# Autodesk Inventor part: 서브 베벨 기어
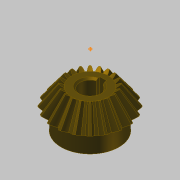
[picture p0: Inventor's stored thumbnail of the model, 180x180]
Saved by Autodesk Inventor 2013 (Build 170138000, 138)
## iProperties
Created: 2016-04
Part Number: 서브 베벨 기어
Material: 강철, 탄소
Document SubType Name: Modeling
Designer: mdu
Categories: <?xml version="1.0" encoding="UTF-16"?> <MemberInstance><Categories><FamilyTemplate><FamilyTemplateParameter ValueType="xs:double" Id="1" ObjectReferenceKey="da
Mass: 135.037 g
Surface Area: 63.6518 cm^2
Volume: 17.1585 cm^3
Density: 7.87 g/cm^3
CustomPartVersion: 1
Author: mdu
Revision Number: 1
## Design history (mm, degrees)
node "맨 위 점"
node "메쉬 평면2"
sketch "톱니 본체 스케치"
  geometry: L1 (0, 0)-(18.003, -31.331); L2 (18.003, -31.331)-(21.664, -28.891); L3 (21.664, -28.891)-(0, 0); L4 (20, -30)-(0, 0); L5 (10.813, -18.818)-(13.012, -17.352); L6 (18.003, -31.331)-(10.813, -18.818); L7 (21.664, -28.891)-(13.012, -17.352); L8 (0, -39.387)-(0, 6.564) reference; L9 (0, -30)-(21.664, -30)
  constraints: 16 end point, 4 point on line, 3 perpendicular, 2 collinear, 1 horizontal alignment, 1 vertical alignment
  dimensions: "d0" = 40 diameter of L4.start L8 (= da_de); "d1" = 36.00616 diameter of L1.end L8 (= da_dfe); "d2" = 43.3282 diameter of L2.end L8 (= da_dae); "d3" = 14.4 distance between parallel lines of L2 L5 (= da_b); "d4" = 28.8906 vertical distance of L2.end L1.start (= da_ve)
revolve "톱니 본체" sketch "톱니 본체 스케치" stored, may be unused: angle "d5" = 90 deg
node "시작점"
node "톱니 평면"
sketch "시작 스케치"
  geometry: L1 (0, -23.505)-(0, 10.645) reference; L2 (-0.834, -2.928)-(0.834, -2.928); A1 r 8.898 centre (-9.698, -3.713) between (-0.834, -2.928) and (-3.903, 3.04); A2 r 8.898 centre (9.698, -3.713) between (3.903, 3.04) and (0.834, -2.928); A3 r 27.357 centre (0, -24.037) between (3.903, 3.04) and (-3.903, 3.04); 1 further point
  constraints: 6 point on circle, 3 centre point, 3 symmetric about line, 2 end point, 1 coincident, 1 perpendicular, 1 other
  dimensions: "d7" = 8.89846 radius of A1 (= fd_rr); "d8" = 9.69794 horizontal distance of point (0, -24.037) A1.centre (= fd_x); "d9" = 20.32439 vertical distance of point (0, -24.037) A1.centre (= fd_y); "d57" = 27.35701 radius of A3 (= 0.5 x fd_dva + 0.3 x da_he); "d58" = 21.10901 distance from line of A3.centre L2 (= 0.5 x fd_dva - 1.12 x da_he)
node "끝점"
  node "끝 평면"
sketch "3D 스케치 오른쪽"
  node "Helical Curve Right" dims "d65" = 229.90621 (computed from da_dm, da_delta, da_beta), "d66" = 31.5, "d67" = 40 (= da_de), "d68" = -5.88003 (= -da_delta), "d69" = 12.16458 (computed from fd_loft, da_delta)
node "끝 평면 오른쪽"
sketch "끝 스케치 오른쪽"
  geometry: L1 (0, -22.649)-(0, 12.15) reference; L2 (-0.497, -1.72)-(0.497, -1.72); A1 r 5.299 centre (-5.775, -2.187) between (-0.497, -1.72) and (-2.324, 1.834); A2 r 5.299 centre (5.775, -2.187) between (2.324, 1.834) and (0.497, -1.72); A3 r 16.291 centre (0, -14.29) between (2.324, 1.834) and (-2.324, 1.834); 1 further point
  constraints: 6 point on circle, 3 centre point, 3 symmetric about line, 2 end point, 1 coincident, 1 perpendicular, 1 other
  dimensions: "d70" = 5.77526 horizontal distance of A3.centre A1.centre (computed from fd_x, fd_ratio); "d71" = 12.10346 vertical distance of point (0, -14.29) A1.centre (computed from fd_y, fd_ratio); "d72" = 5.29916 radius of A1 (computed from fd_rr, fd_ratio); "d73" = 12.57071 distance from line of point (0, -14.29) L2 (computed from d58, fd_ratio); "d74" = 16.29149 radius of A3 (computed from d57, fd_ratio)
feature "로프트 오른쪽" sketch "끝 스케치 오른쪽" dims "d75" = 0, "d77" = 0, "d79" = 0, "d80" = 90 deg, "d85" = 20, "d92" = 90 deg, "d93" = 90 deg, "da_teethtype" = 0 [user parameter]
sketch "3D 스케치 왼쪽"
  node "Helical Curve Left" dims "d26" = 229.90621 (computed from da_dm, da_delta, da_beta), "d27" = 12.16458 (computed from fd_loft, da_delta), "d28" = 40 (= da_de), "d29" = -5.88003 (= -da_delta)
node "끝 평면 왼쪽"
sketch "끝 스케치 왼쪽" dims "d56" = 10.82768 (derived)
  geometry: L1 (0, -35.087)-(0, 18.089) reference; L2 (-0.497, -1.716)-(0.497, -1.716); A1 r 5.299 centre (-5.775, -2.183) between (-0.497, -1.716) and (-2.324, 1.838); A2 r 5.299 centre (5.775, -2.183) between (2.324, 1.838) and (0.497, -1.716); A3 r 16.291 centre (0, -14.287) between (2.324, 1.838) and (-2.324, 1.838); 2 further points; 1 other entity
  constraints: 6 point on circle, 3 centre point, 3 symmetric about line, 2 end point, 1 coincident, 2 other
  dimensions: "d30" = 5.29916 radius of A1 (computed from fd_rr, fd_ratio); "d31" = 5.77526 horizontal distance of point (0, -14.287) A1.centre (computed from fd_x, fd_ratio); "d32" = 12.10346 vertical distance of A1.centre point (0, -14.287) (computed from fd_y, fd_ratio); "d61" = 16.29149 radius of A3 (computed from d57, fd_ratio); "d62" = 12.57071 distance from line of point (0, -14.287) L2 (computed from d58, fd_ratio)
feature "로프트 왼쪽" sketch "끝 스케치 왼쪽" dims "d35" = 0, "d37" = 0, "d39" = 0, "d40" = 90 deg, "d84" = 10, "d90" = 90 deg, "d91" = 90 deg, "da_teethtype" = 0 [user parameter]
sketch "본체 스케치"
  geometry: L1 (0, -35.038)-(0, -19.531) reference; L2 (18.003, -31.331)-(10.813, -18.818) reference; L3 (10.813, -18.818)-(0, -18.818); L4 (18.003, -31.331)-(0, -31.331)
  constraints: 4 end point, 2 perpendicular, 2 point on line
revolve "본체 고정" sketch "본체 스케치" stored, may be unused: angle "d46" = 90 deg
feature "피치 지름" dims angle "d47" = 90 deg
sketch "스케치8"
  geometry: C1 r 17 at (0, 0); 1 further point
  constraints: 1 centre point, 1 coincident
  dimensions: "d94" = 34 diameter of C1
extrude "돌출1" join sketch "스케치8" distance "d95" = 10; taper "d96" = 0 deg
sketch "스케치9"
  geometry: 1 further point
hole "구멍1" sketch "스케치9" at (0, 0) diameter "d97" = 12; stored, may be unused: countersink angle "d101" = 90 deg, drill point angle "d103" = 118 deg; dims "d98" = 6, "d99" = 4, "d100" = 2, "d102" = 8
sketch "스케치10"
  geometry: 1 further point
sketch "스케치11"
  geometry: 1 further point
sketch "스케치12"
  geometry: L1 (-2, 5.657)-(-2, 7.8); L2 (-2, 7.8)-(2, 7.8); L3 (2, 7.8)-(2, 5.657); A1 r 6 centre (0, 0) between (-2, 5.657) and (2, 5.657) reference; 1 further point
  constraints: 6 end point, 2 parallel, 2 point on circle, 1 perpendicular, 1 vertical
  dimensions: "d104" = 4 distance of L1.end L2.end; "d105" = 13.8 dimension on A1 L2
extrude "돌출2" cut sketch "스케치12" stored distance "d106" = 7; taper "d107" = 0 deg
chamfer "모따기1" distance "d108" = 1; stored, may be unused: second distance "d109" = 2, angle "d110" = 45 deg
body "Solid1"
feature "로프트" dims "d17" = 0, "d18" = 90 deg, "d19" = 0, "d20" = 90 deg, "d89" = 0, "da_teethtype" = 0 [user parameter]
pattern_circular "원형 패턴" dims angle "d22" = 360 deg, "d88" = 0, "da_teethtype" = 0 [user parameter]
pattern_circular "원형 패턴 오른쪽" dims angle "d82" = 360 deg, "da_teethtype" = 0 [user parameter]
pattern_circular "원형 패턴 왼쪽" dims angle "d42" = 360 deg, "da_teethtype" = 0 [user parameter]
sketch "끝 스케치"
  geometry: L1 (0, -15.359)-(0, 6.983) reference; L2 (-0.497, -1.72)-(0.497, -1.72); A1 r 5.299 centre (-5.775, -2.187) between (-0.497, -1.72) and (-2.324, 1.834); A2 r 5.299 centre (5.775, -2.187) between (2.324, 1.834) and (0.497, -1.72); A3 r 16.291 centre (0, -14.29) between (2.324, 1.834) and (-2.324, 1.834); 1 further point
  constraints: 6 point on circle, 3 centre point, 3 symmetric about line, 2 end point, 1 coincident, 1 other
  dimensions: "d12" = 5.29916 radius of A1 (computed from fd_rr, fd_ratio); "d15" = 5.77526 horizontal distance of A1.centre point (0, -14.29) (computed from fd_x, fd_ratio); "d16" = 12.10346 vertical distance of A1.centre point (0, -14.29) (computed from fd_y, fd_ratio); "d59" = 16.29149 radius of A3 (computed from d57, fd_ratio); "d60" = 12.57071 distance from line of A3.centre L2 (computed from d58, fd_ratio)
sketch "Sketch6"
  geometry: L1 (20, -30)-(0, 0) reference; L2 (0, -37.8)-(0, 6.3) reference
body "Srf1"
other parameters: "da_b" = 14.4 [user parameter; used in 2 equation terms], "da_de" = 40 [user parameter; used in 4 equation terms], "da_dae" = 43.3282 [user parameter; used in 2 equation terms], "da_dfe" = 36.00616 [user parameter; used in 1 equation term], "da_le" = 36.05551 [user parameter; used in 1 equation term], "da_omega" = 90 deg [user parameter; used in 1 equation term], "da_beta" = 0 [user parameter; used in 2 equation terms], "da_delta" = 5.88003 [user parameter; used in 8 equation terms], "da_alpha" = 20 deg [user parameter; used in 2 equation terms], "da_he" = 4.4 [user parameter; used in 4 equation terms], "da_ve" = 28.8906 [user parameter; used in 1 equation term], "fd_dv" = 48.07402 (computed from da_de, da_delta) [user parameter; used in 1 equation term], "fd_dva" = 52.07402 (computed from da_dae, da_delta) [user parameter; used in 3 equation terms], "fd_dvb" = 45.1748 (computed from fd_dv, da_alpha) [user parameter; used in 2 equation terms], "da_zv" = 240.37008 [user parameter; used in 1 equation term], "fd_loft" = 14.62 (= da_b + 0.05 x da_he) [user parameter; used in 4 equation terms], "fd_ratio" = 5.95514 (computed from da_le, fd_loft) [user parameter; used in 15 equation terms], "fd_rr" = 8.89846 (computed from fd_dd, fd_dvb) [user parameter; used in 6 equation terms], "fd_angle" = 0.66075 (computed from da_zv) [user parameter; used in 4 equation terms], "fd_x1" = 1.58709 (computed from da_dvw, fd_angle) [user parameter; used in 1 equation term], "fd_y1" = 23.98456 (computed from da_dvw, fd_angle) [user parameter; used in 1 equation term], "fd_x2" = 8.11084 (computed from fd_rr, fd_angle2, fd_angle) [user parameter; used in 1 equation term], "fd_y2" = 3.66016 (computed from fd_rr, fd_angle2, fd_angle) [user parameter; used in 1 equation term], "fd_x" = 9.69794 (= fd_x1 + fd_x2) [user parameter; used in 4 equation terms], "fd_y" = 20.32439 (= fd_y1 - fd_y2) [user parameter; used in 4 equation terms], "fd_angle2" = 3.57832 (computed from fd_dvb, fd_dd, da_alpha) [user parameter; used in 2 equation terms], "fd_dd" = 48.55402 (= fd_dva - 0.8 x da_he) [user parameter; used in 2 equation terms], "da_dvw" = 48.07402 [user parameter; used in 2 equation terms], "d11" = 14.62 (= fd_loft), "da_dm" = 32.01232 [user parameter; used in 2 equation terms], "da_x" = 0 [user parameter], "da_m" = 2 [user parameter], "d48" = 0, "d49" = 0, "d50" = 90 deg (= da_omega), "d51" = 9 deg (computed from da_z), "d52" = 0, "d53" = 0, "d54" = 0
